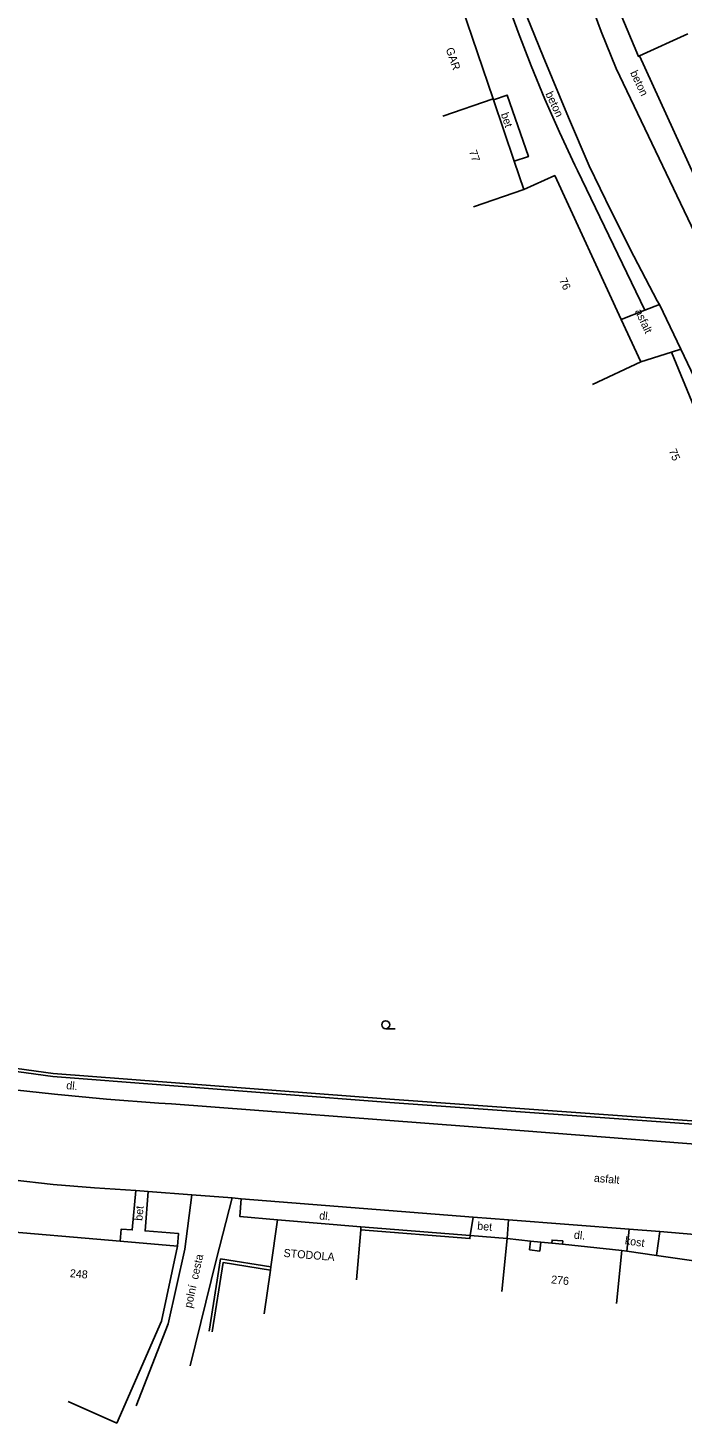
# Model space of a CAD drawing. Extents: x -544674 to -541478, y -1199076 to -1195527.
# Drawn here: x -542745.6 to -542684.3, y -1198257.3 to -1198126.6 of the extents above; entities that cross this region are included whole.
import ezdxf

# ---------------------------------------------------------------- set-up
doc = ezdxf.new("R2010")
doc.units = 0
for name, color, linetype in [('BUDOVY_MĚŘ', 7, 'Continuous'), ('POMOC_POPIS', 7, 'Continuous'), ('ROZHRANÍ_PLOCH', 7, 'Continuous'), ('ZN_DOPLŇKOVÉ', 7, 'Continuous'), ('ZN_KULTUR', 7, 'Continuous'), ('Č_POPIS_ORIENT', 7, 'Continuous')]:
    doc.layers.add(name, color=color, linetype=linetype)

msp = doc.modelspace()

# ---------------------------------------------------------------- linework, layer by layer
at = {"layer": 'BUDOVY_MĚŘ'}
for points in [[(-542692.9, -1198118.51), (-542688.39, -1198129.23), (-542688.3, -1198129.19)], [(-542704.96, -1198124.59), (-542702, -1198133.19)], [(-542683.75, -1198127.11), (-542688.3, -1198129.19)], [(-542688.3, -1198129.19), (-542679.92, -1198147.51)], [(-542706.73, -1198134.82), (-542702, -1198133.19)], [(-542702, -1198133.19), (-542701.97, -1198133.29)], [(-542701.97, -1198133.29), (-542700.03, -1198139.05)], [(-542700.03, -1198139.05), (-542699.13, -1198141.71)], [(-542699.13, -1198141.71), (-542696.24, -1198140.4), (-542690.01, -1198153.88)], [(-542703.87, -1198143.31), (-542699.13, -1198141.71)], [(-542690.01, -1198153.88), (-542688.17, -1198157.86)], [(-542688.17, -1198157.86), (-542685.28, -1198156.93)], [(-542685.28, -1198156.93), (-542683.18, -1198162.08)], [(-542692.71, -1198159.96), (-542688.17, -1198157.86)], [(-542722.86, -1198242.65), (-542722.24, -1198238.24)], [(-542722.24, -1198238.24), (-542714.41, -1198238.88)], [(-542749.84, -1198244.6), (-542749.43, -1198239.18), (-542736.99, -1198240.24)], [(-542714.43, -1198239.18), (-542714.82, -1198243.86)], [(-542714.41, -1198238.88), (-542714.43, -1198239.18)], [(-542731.62, -1198240.7), (-542733.1, -1198247.74), (-542737.31, -1198257.28), (-542741.88, -1198255.26)], [(-542736.99, -1198240.24), (-542731.62, -1198240.7)], [(-542701.21, -1198244.96), (-542700.7, -1198239.99)], [(-542700.7, -1198239.99), (-542698.51, -1198240.22)], [(-542698.51, -1198240.22), (-542697.55, -1198240.32)], [(-542697.55, -1198240.32), (-542696.52, -1198240.42)], [(-542696.52, -1198240.42), (-542695.52, -1198240.52)], [(-542695.52, -1198240.52), (-542689.95, -1198241.1)], [(-542690.46, -1198246.07), (-542689.95, -1198241.1)], [(-542689.95, -1198241.1), (-542689.47, -1198241.17)], [(-542689.47, -1198241.17), (-542686.7, -1198241.57)], [(-542686.7, -1198241.57), (-542673.39, -1198243.48)], [(-542723.48, -1198247.05), (-542722.9, -1198242.94)], [(-542722.9, -1198242.94), (-542722.86, -1198242.65)]]:
    msp.add_lwpolyline(points, dxfattribs=at)
at = {"layer": 'ROZHRANÍ_PLOCH'}
for points in [[(-542694.69, -1198117.2), (-542694.84, -1198117.59), (-542694.92, -1198118), (-542694.93, -1198118.43), (-542694.85, -1198118.85), (-542694.72, -1198119.19), (-542691.89, -1198126.89), (-542690.47, -1198130.35), (-542681.77, -1198148.59)], [(-542687.78, -1198153.01), (-542694.09, -1198139.93), (-542694.35, -1198139.41), (-542695.79, -1198136.34), (-542697.16, -1198133.25), (-542698.45, -1198130.12), (-542699.67, -1198126.97), (-542700.82, -1198123.78)], [(-542699.65, -1198123.51), (-542697.34, -1198129.25), (-542694.96, -1198134.96), (-542693.01, -1198139.47), (-542690.95, -1198143.73), (-542688.82, -1198147.95), (-542686.62, -1198152.13), (-542686.43, -1198152.48)], [(-542700.03, -1198139.05), (-542698.71, -1198138.61), (-542700.69, -1198132.86), (-542701.97, -1198133.29)], [(-542690.01, -1198153.88), (-542687.78, -1198153.01)], [(-542687.78, -1198153.01), (-542686.43, -1198152.48)], [(-542686.43, -1198152.48), (-542684.42, -1198156.65)], [(-542684.42, -1198156.65), (-542685.28, -1198156.93)], [(-542684.42, -1198156.65), (-542682.22, -1198161.24), (-542678.08, -1198170.03), (-542676.96, -1198172.44)], [(-542821.53, -1198198.27), (-542799.52, -1198209.99), (-542796.51, -1198211.57), (-542793.46, -1198213.08), (-542790.38, -1198214.52), (-542787.27, -1198215.89), (-542784.12, -1198217.18), (-542780.95, -1198218.4), (-542780.17, -1198218.68), (-542776.99, -1198219.77), (-542773.79, -1198220.78), (-542770.57, -1198221.71), (-542767.32, -1198222.57), (-542764.06, -1198223.35), (-542760.77, -1198224.05), (-542757.82, -1198224.61), (-542752.94, -1198225.31), (-542748.06, -1198225.92), (-542743.16, -1198226.46), (-542738.26, -1198226.92), (-542733.35, -1198227.29), (-542732.18, -1198227.37), (-542704.32, -1198229.5), (-542679.04, -1198231.46)], [(-542735.53, -1198235.48), (-542739.4, -1198235.23), (-542743.27, -1198234.91), (-542747.13, -1198234.5), (-542748.96, -1198234.27)], [(-542736.99, -1198240.24), (-542736.89, -1198239.11), (-542735.86, -1198239.18), (-542735.53, -1198235.48)], [(-542735.53, -1198235.48), (-542734.37, -1198235.57)], [(-542734.37, -1198235.57), (-542734.66, -1198239.27), (-542731.52, -1198239.52), (-542731.62, -1198240.7)], [(-542734.37, -1198235.57), (-542730.27, -1198235.9)], [(-542730.27, -1198235.9), (-542730.94, -1198240.97), (-542732.48, -1198247.99), (-542735.48, -1198255.65)], [(-542726.49, -1198236.19), (-542727.96, -1198241.88), (-542730.42, -1198251.93)], [(-542726.49, -1198236.19), (-542730.27, -1198235.9)], [(-542725.63, -1198236.26), (-542726.49, -1198236.19)], [(-542722.24, -1198238.24), (-542725.76, -1198237.93), (-542725.63, -1198236.26)], [(-542703.9, -1198237.99), (-542725.63, -1198236.26)], [(-542703.9, -1198237.99), (-542704.17, -1198239.7)], [(-542700.57, -1198238.24), (-542703.9, -1198237.99)], [(-542700.57, -1198238.24), (-542700.7, -1198239.99)], [(-542689.25, -1198239.11), (-542700.57, -1198238.24)], [(-542689.47, -1198241.17), (-542689.25, -1198239.11)], [(-542686.38, -1198239.34), (-542689.25, -1198239.11)], [(-542686.7, -1198241.57), (-542686.38, -1198239.34)], [(-542663.15, -1198241.68), (-542668.12, -1198240.88), (-542686.38, -1198239.34)], [(-542698.6, -1198241.06), (-542698.51, -1198240.22)], [(-542697.63, -1198241.16), (-542697.55, -1198240.32)], [(-542695.52, -1198240.52), (-542695.49, -1198240.21), (-542696.49, -1198240.13), (-542696.52, -1198240.42)], [(-542697.63, -1198241.16), (-542698.6, -1198241.06)]]:
    msp.add_lwpolyline(points, dxfattribs=at)
at = {"layer": 'ZN_DOPLŇKOVÉ'}
for points in [[(-542681.48, -1198229.4), (-542711.71, -1198227.24), (-542743.3, -1198224.82), (-542758.12, -1198222.79), (-542764.73, -1198221.38), (-542779.61, -1198217.08), (-542787.74, -1198213.81), (-542790.45, -1198212.62)], [(-542681.62, -1198229.09), (-542711.69, -1198226.94), (-542743.27, -1198224.52), (-542758.07, -1198222.49), (-542764.66, -1198221.09), (-542779.51, -1198216.8), (-542787.1, -1198213.74)], [(-542704.17, -1198239.7), (-542704.19, -1198240), (-542714.43, -1198239.18)], [(-542704.17, -1198239.7), (-542714.41, -1198238.88)], [(-542700.7, -1198239.99), (-542704.17, -1198239.7)], [(-542722.86, -1198242.65), (-542727.57, -1198241.89), (-542728.66, -1198248.68)], [(-542722.9, -1198242.94), (-542727.32, -1198242.23), (-542728.36, -1198248.73)]]:
    msp.add_lwpolyline(points, dxfattribs=at)
at = {"layer": 'ZN_KULTUR'}
msp.add_line((-542712.09, -1198220.335), (-542711.215, -1198220.335), dxfattribs=at)
msp.add_circle((-542712.09, -1198219.96), 0.375, dxfattribs=at)

# ---------------------------------------------------------------- texts
at = {"layer": 'POMOC_POPIS'}
for s, rotation, p in [('GAR', 289.00003, (-542706.47, -1198128.54)), ('beton', 295.5, (-542689.19, -1198130.76)), ('beton', 295.27002, (-542697.13, -1198132.73)), ('bet', 288.61998, (-542701.31, -1198134.63)), ('asfalt', 294.80999, (-542688.74, -1198153.09)), ('dl.', 354.47999, (-542742.07, -1198225.99)), ('asfalt', 355.17997, (-542692.59, -1198234.67)), ('bet', 84.90003, (-542734.91, -1198238.35)), ('dl.', 354.10001, (-542718.35, -1198238.19)), ('bet', 355.22002, (-542703.53, -1198239.16)), ('dl.', 354.10001, (-542694.47, -1198239.99)), ('kost', 351.83001, (-542689.7, -1198240.52)), ('polní  cesta', 77.62999, (-542730.29, -1198246.55)), ('STODOLA', 355.32998, (-542721.69, -1198241.7))]:
    msp.add_text(s, height=0.75, rotation=rotation, dxfattribs=at).set_placement(p)
at = {"layer": 'Č_POPIS_ORIENT'}
for s, rotation, p in [('77', 288.61998, (-542704.29, -1198138.13)), ('76', 294.80999, (-542695.85, -1198150.19)), ('75', 292.2, (-542685.56, -1198166.17)), ('248', 355.11999, (-542741.73, -1198243.6)), ('276', 354.10001, (-542696.61, -1198244.18))]:
    msp.add_text(s, height=0.75, rotation=rotation, dxfattribs=at).set_placement(p)

doc.saveas('drawing.dxf')
